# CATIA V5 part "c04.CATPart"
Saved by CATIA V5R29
Part number: c04
Source: Unknown
Bounding box of the stored display mesh (mm): x -18 to 0, y -67.553 to 154.447, z -197.568 to -77.568
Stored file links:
  C:\가치같이\SmartFactory_BoxErectorConveyor\Boxing(under)\c04.CATPart
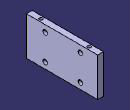
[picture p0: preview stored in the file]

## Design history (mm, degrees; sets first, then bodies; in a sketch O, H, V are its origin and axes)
Body1 (main body)
  Solid1 "PartBody": solid without history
